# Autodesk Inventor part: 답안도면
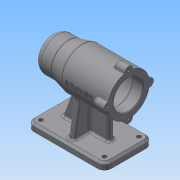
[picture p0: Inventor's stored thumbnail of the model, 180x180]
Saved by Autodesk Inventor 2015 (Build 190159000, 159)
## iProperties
Created: 2019-07
Part Number: 답안도면
Material: 일반
Document SubType Name: Modeling
Designer: user
Density: 1 g/cm^3
Appearance: 기본값
Author: user
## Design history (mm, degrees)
sketch "스케치1"
  geometry: L1 (0, 0)-(0, 30); L2 (0, 30)-(-67, 30); L3 (-67, 30)-(-87, 25); L4 (-87, 25)-(-112, 25); L5 (-112, 25)-(-112, 0); L6 (-112, 0)-(0, 0)
  constraints: 12 end point, 3 perpendicular, 1 parallel, 1 vertical
  dimensions: "d0" = 60 diameter of L2 L6; "d1" = 25 distance of L3.end L4.end; "d2" = 45 horizontal distance of L2.end L4.end; "d3" = 50 diameter of L4 L6; "d4" = 112 distance of L5.end L1.start
revolve "회전1" sketch "스케치1" stored, may be unused: angle "d5" = 90 deg
sketch "스케치2"
  geometry: L1 (0, 0)-(106, 0); L2 (106, 0)-(106, 10.5); L3 (106, 10.5)-(103, 10.5); L4 (103, 10.5)-(103, 16); L5 (103, 16)-(99, 16); L6 (99, 16)-(99, 17.5); L7 (99, 17.5)-(81, 17.5); L8 (81, 17.5)-(81, 21); L9 (81, 21)-(69, 21); L10 (69, 21)-(69, 24); L11 (69, 24)-(15, 24); L12 (15, 24)-(15, 21); L13 (0, 30)-(0, -30) reference; L14 (15, 21)-(0, 21)
  constraints: 26 end point, 12 perpendicular, 2 point on line, 1 horizontal
  dimensions: "d6" = 3 distance of L2.end L3.end; "d7" = 4 distance of L4.end L5.end; "d8" = 18 distance of L6.end L7.end; "d9" = 12 distance of L8.end L9.end; "d10" = 54 distance of L10.end L11.end; "d11" = 15 distance of L12.end L14.end; "d12" = 21 diameter of L3 L1; "d13" = 32 diameter of L5 L1; "d14" = 35 diameter of L7 L1; "d15" = 42 diameter of L9 L1; "d16" = 48 diameter of L11 L1
revolve "회전2" sketch "스케치2" stored, may be unused: angle "d17" = 90 deg
fillet "모깎기1" dims "d18" = 3
fillet "모깎기2" dims "d19" = 0.3
chamfer "모따기1" distance "d20" = 1; stored, may be unused: second distance "d21" = 2, angle "d22" = 45 deg
fillet "모깎기3" dims "d23" = 10
fillet "모깎기4" dims "d24" = 3
node "작업 평면1"
sketch "스케치3"
  geometry: L1 (-112, -35)-(0, -35); L2 (0, -35)-(0, 35); L3 (0, 35)-(-112, 35); L4 (-112, 35)-(-112, -35); L5 (-112, -35)-(0, 35); L6 (0, -35)-(-112, 35); 5 further points
  constraints: 12 end point, 5 midpoint, 2 coincident, 2 parallel, 1 horizontal, 1 perpendicular, 1 vertical alignment
  dimensions: "d26" = 70 distance of L1.end L2.end; "d27" = 112 distance of L2.end L3.end
extrude "돌출1" join sketch "스케치3" distance "d28" = 10; taper "d29" = 0 deg
node "작업 평면2"
fillet "모깎기5" dims "d45" = 10
sketch "스케치7"
  geometry: C1 r 6 at (-30, 0); 1 further point
  constraints: 2 horizontal alignment, 1 centre point, 1 other
  dimensions: "d57" = 12 diameter of C1
extrude "돌출3" join sketch "스케치7" distance "d58" = 16; taper "d59" = 0 deg
sketch "스케치8"
  geometry: A1 r 6 centre (0, 0) between (0.6, 5.97) and (0.6, -5.97) reference; 1 further point
  constraints: 1 coincident
hole "구멍2" sketch "스케치8" at (0, 0) diameter "d60" = 3.242; stored, may be unused: countersink angle "d64" = 90 deg, drill point angle "d66" = 118 deg; dims "d61" = 8, "d62" = 4, "d63" = 2, "d65" = 11
fillet "모깎기9" dims "d70" = 3
fillet "모깎기10" dims "d71" = 1
fillet "모깎기11" dims "d72" = 3
fillet "모깎기12" dims "d73" = 1
node "작업 평면4"
sketch "스케치10"
  geometry: 2 further points
  constraints: 1 horizontal alignment, 1 other
  dimensions: "d76" = 42 distance of point (0, 0) point (-42, 0)
feature "엠보싱1" sketch "스케치10" dims "d0" = 60, "d1" = 25, "d2" = 45, "d3" = 50, "d4" = 112, "d6" = 3, "d7" = 4, "d8" = 18, "d9" = 12, "d10" = 54, "d11" = 15, "d12" = 21, "d13" = 32, "d14" = 35, "d15" = 42, "d16" = 48, "d77" = 0.5, "d78" = 0
chamfer "모따기2" distance "d79" = 3; stored, may be unused: second distance "d80" = 2, angle "d81" = 45 deg
sketch "스케치11"
  geometry: A1 r 7 centre (-10, -25) between (-10, -32) and (-3, -25) reference; A2 r 7 centre (-10, 25) between (-3, 25) and (-10, 32) reference; A3 r 7 centre (-102, 25) between (-102, 32) and (-109, 25) reference; A4 r 7 centre (-102, -25) between (-109, -25) and (-102, -32) reference; 5 further points
  constraints: 4 coincident
hole "구멍3" sketch "스케치11" at (-102, 25), (-10, 25), (-10, -25), (-102, -25) diameter "d82" = 6; stored, may be unused: countersink angle "d86" = 90 deg, drill point angle "d88" = 0 deg; dims "d83" = 6, "d84" = 4, "d85" = 2, "d87" = 8
sketch "스케치12"
  geometry: L1 (109, -70)-(112, -73) reference; L2 (112, -73)-(112, -80) reference; L3 (112, -80)-(0, -80) reference; L4 (0, -80)-(0, -73) reference; L5 (0, -73)-(3, -70) reference; L6 (3, -70)-(109, -70) reference; L7 (103, -15.7)-(103, -10.5) reference; L8 (106, -7.5)-(106, 7.5) reference; L9 (103, 10.5)-(103, 15.7) reference; L10 (102.7, 16)-(99, 16) reference; L11 (99, 16)-(99, 17.2) reference; L12 (98.7, 17.5)-(81, 17.5) reference; L13 (81, 17.5)-(81, 20.7) reference; L14 (80.7, 21)-(69, 21) reference; L15 (66, 24)-(18, 24) reference; L16 (15, 21)-(1, 21) reference; L17 (1, 21)-(0, 22) reference; L18 (0, 22)-(0, 28.379) reference; L19 (0, 28.379)-(11, 28.379) reference; L20 (11, 28.379)-(11.974, 30) reference; L21 (11.974, 30)-(11, 31.621) reference; L22 (11, 31.621)-(0, 31.621) reference; L23 (0, 31.621)-(0, 36) reference; L24 (0, 36)-(13, 36) reference; L25 (16, 33)-(16, 31) reference; L26 (17, 30)-(66.631, 30) reference; L27 (67.358, 29.91)-(86.642, 25.09) reference; L28 (87.369, 25)-(102, 25) reference; L29 (112, 15)-(112, -15) reference; L30 (102, -25)-(87.369, -25) reference; L31 (86.642, -25.09)-(67.358, -29.91) reference; L32 (66.631, -30)-(17, -30) reference; L33 (16, -31)-(16, -33) reference; L34 (13, -36)-(0, -36) reference; L35 (0, -36)-(0, -31.621) reference; L36 (0, -31.621)-(11, -31.621) reference; L37 (11, -31.621)-(11.974, -30) reference; L38 (11.974, -30)-(11, -28.379) reference; L39 (11, -28.379)-(0, -28.379) reference; L40 (0, -28.379)-(0, -22) reference; L41 (0, -22)-(1, -21) reference; L42 (1, -21)-(15, -21) reference; L43 (18, -24)-(66, -24) reference; L44 (69, -21)-(80.7, -21) reference; L45 (81, -20.7)-(81, -17.5) reference; L46 (81, -17.5)-(98.7, -17.5) reference; L47 (99, -17.2)-(99, -16) reference; L48 (99, -16)-(102.7, -16) reference; L49 (92, -70)-(76.57, -27.607); L50 (25, -70)-(25, -30); L51 (92, -70)-(25, -70); A1 r 0.3 centre (102.7, -15.7) between (102.7, -16) and (103, -15.7) reference; A2 r 3 centre (103, -7.5) between (103, -10.5) and (106, -7.5) reference; A3 r 3 centre (103, 7.5) between (106, 7.5) and (103, 10.5) reference; A4 r 0.3 centre (102.7, 15.7) between (103, 15.7) and (102.7, 16) reference; A5 r 0.3 centre (98.7, 17.2) between (99, 17.2) and (98.7, 17.5) reference; A6 r 0.3 centre (80.7, 20.7) between (81, 20.7) and (80.7, 21) reference; A7 r 3 centre (66, 21) between (69, 21) and (66, 24) reference; A8 r 3 centre (18, 21) between (18, 24) and (15, 21) reference; A9 r 3 centre (13, 33) between (16, 33) and (13, 36) reference; A10 r 1 centre (17, 31) between (16, 31) and (17, 30) reference; A11 r 3 centre (66.631, 27) between (67.358, 29.91) and (66.631, 30) reference; A12 r 3 centre (87.369, 28) between (86.642, 25.09) and (87.369, 25) reference; A13 r 10 centre (102, 15) between (112, 15) and (102, 25) reference; A14 r 10 centre (102, -15) between (102, -25) and (112, -15) reference; A15 r 3 centre (87.369, -28) between (87.369, -25) and (86.642, -25.09) reference; A16 r 3 centre (66.631, -27) between (66.631, -30) and (67.358, -29.91) reference; A17 r 1 centre (17, -31) between (17, -30) and (16, -31) reference; A18 r 3 centre (13, -33) between (13, -36) and (16, -33) reference; A19 r 3 centre (18, -21) between (15, -21) and (18, -24) reference; A20 r 3 centre (66, -21) between (66, -24) and (69, -21) reference; A21 r 0.3 centre (80.7, -20.7) between (80.7, -21) and (81, -20.7) reference; A22 r 0.3 centre (98.7, -17.2) between (98.7, -17.5) and (99, -17.2) reference; 1 further point
  constraints: 6 end point, 4 point on line, 1 collinear, 1 perpendicular
  dimensions: "d89" = 25 distance from line of L4 L50.start; "d90" = 20 distance from line of L2 L49.start; "d91" = 110 deg angle of L6 L49
feature "리브2" sketch "스케치12" dims "d92" = 1, "d93" = 8, "d94" = 0, "d95" = 0, "d96" = 1, "d97" = 1
node "작업 평면5"
sketch "스케치13"
  geometry: L1 (32, -70)-(35, -73) reference; L2 (35, -73)-(35, -80) reference; L3 (35, -80)-(-35, -80) reference; L4 (-35, -80)-(-35, -73) reference; L5 (-35, -73)-(-32, -70) reference; L6 (-32, -70)-(-4, -70) reference; L7 (-4, -70)-(-4, -29.732) reference; L8 (-29.999, 0.254)-(-30.499, 0.259) reference; L9 (-30.493, 0.659)-(-29.993, 0.648) reference; L10 (4, -29.732)-(4, -70) reference; L11 (4, -70)-(32, -70) reference; L12 (-28, -70)-(-19.654, -22.666); C1 r 24 at (0, 0) reference; A1 r 30 centre (0, 0) between (-29.999, 0.254) and (-4, -29.732) reference; A2 r 30.5 centre (0, 0) between (-30.493, 0.659) and (-30.499, 0.259) reference; A3 r 30 centre (0, 0) between (4, -29.732) and (-29.993, 0.648) reference; 1 further point
  constraints: 2 end point, 1 point on circle, 1 point on line
  dimensions: "d99" = 7 distance from line of L12.start L4; "d100" = 100 deg angle of L6 L12
feature "리브3" sketch "스케치13" dims "d101" = 1, "d102" = 8, "d103" = 0, "d104" = 0, "d105" = 1, "d106" = 1
fillet "모깎기13" dims "d107" = 3
fillet "모깎기14" dims "d108" = 3
node "솔리드1"
pattern_circular "원형 패턴1" dims angle "d68" = 360 deg
mirror "대칭2"
node "절단 모서리 투영2"
node "절단 모서리 투영3"
other parameters: "d36" = -56, "d98" = -56
